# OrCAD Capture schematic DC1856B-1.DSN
size Custom
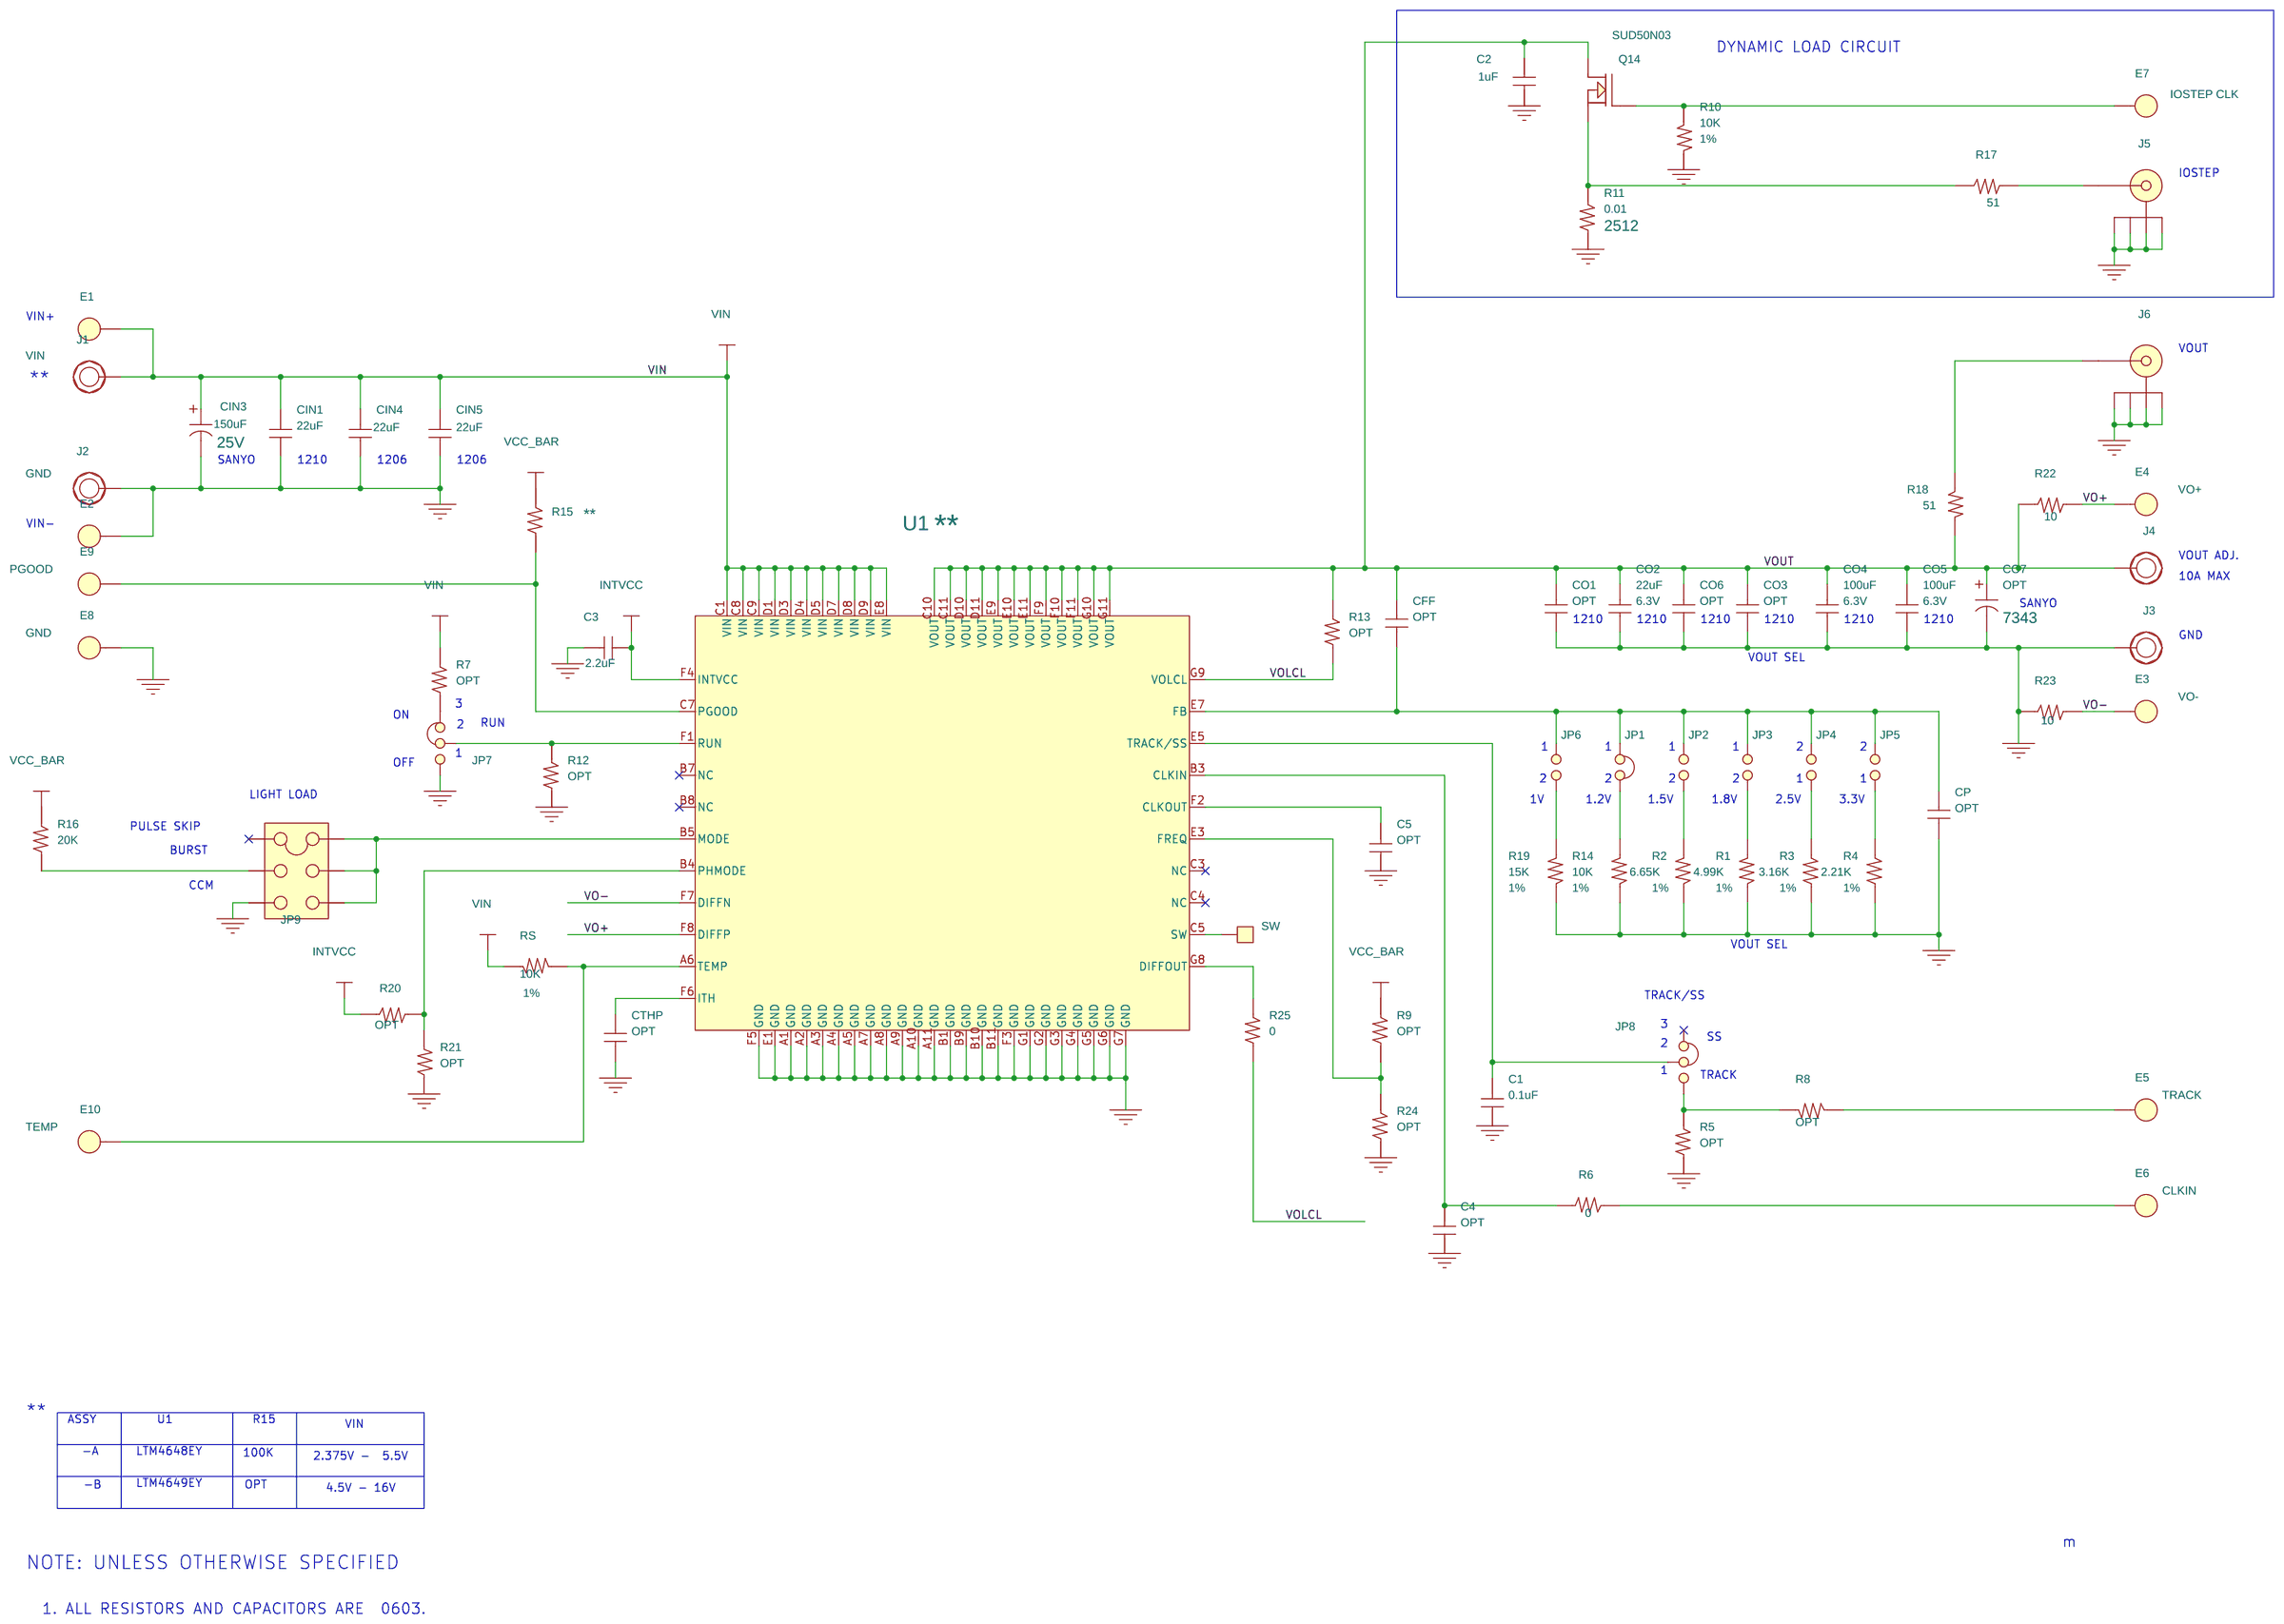
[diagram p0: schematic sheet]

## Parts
C1  0.1uF  [LG0603]
C2  1uF  [LG0603]
C3  2.2uF  [LG0603]
C4  OPT  [LG0603]
C5  OPT  [LG0603]
CFF  OPT  [LG0603]
CIN1  22uF  [LG1210]
CIN3  150uF  [CAP\SANYO\SVPA_E7]
CIN4  22uF  [1206]
CIN5  22uF  [1206]
CO1  OPT  [LG1210]
CO2  22uF  [LG1210]
CO3  OPT  [LG1210]
CO4  100uF  [LG1210]
CO5  100uF  [LG1210]
CO6  OPT  [LG1210]
CO7  OPT  [7343]
CP  OPT  [LG0603]
CTHP  OPT  [LG0603]
E1  PAD150-094  [TP\MMX\2501-2]
E2  PAD150-094  [TP\MMX\2501-2]
E3  PAD150-094  [TP\MMX\2501-2]
E4  PAD150-094  [TP\MMX\2501-2]
E5  PAD150-094  [TP\MMX\2501-2]
E6  PAD150-094  [TP\MMX\2501-2]
E7  PAD150-094  [TP\MMX\2501-2]
E8  PAD150-094  [TP\MMX\2501-2]
E9  PAD150-094  [TP\MMX\2501-2]
E10  PAD150-094  [TP\MMX\2501-2]
J1  Banana Jack  [RP325/205]
J2  Banana Jack  [RP325/205]
J3  Banana Jack  [RP325/205]
J4  Banana Jack  [RP325/205]
J5  XXX  [BNC5]
J6  XXX  [BNC5]
JP1  JMP1X2  [SIP\2P\2MM]
JP2  JMP1X2  [SIP\2P\2MM]
JP3  JMP1X2  [SIP\2P\2MM]
JP4  JMP1X2  [SIP\2P\2MM]
JP5  JMP1X2  [SIP\2P\2MM]
JP6  JMP1X2  [SIP\2P\2MM]
JP7  JMP1X3  [JUMPER3\2MM]
JP8  JMP1X3  [JUMPER3\2MM]
JP9  hdr2X3  [HDR\3X2\2MM]
Q14  SUD50N03  [TO-252]
R1  4.99K  [LG0603]
R2  6.65K  [LG0603]
R3  3.16K  [LG0603]
R4  2.21K  [LG0603]
R5  OPT  [LG0603]
R6  0  [LG0603]
R7  OPT  [LG0603]
R8  OPT  [LG0603]
R9  OPT  [LG0603]
R10  10K  [LG0603]
R11  0.01  [2512]
R12  OPT  [LG0603]
R13  OPT  [LG0603]
R14  10K  [LG0603]
R15  **  [LG0603]
R16  20K  [LG0603]
R17  51  [LG0603]
R18  51  [LG0603]
R19  15K  [LG0603]
R20  OPT  [LG0603]
R21  OPT  [LG0603]
R22  10  [LG0603]
R23  10  [LG0603]
R24  OPT  [LG0603]
R25  0  [LG0603]
RS  10K  [LG0603]
SW  SW  [RP062]
U1  **  [BGA68-15X9X4.92]
XJP1  SHUNT  [NONE]
XJP7  SHUNT  [NONE]
XJP8  SHUNT  [NONE]
XJP11  SHUNT  [NONE]

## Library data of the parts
C1 CP CTHP = CAP-NP: CAP, 0603 OPTION; Part Number: OPTION
C2 = CAP-NP: CAP, 0603 1uF 20% 10V X5R; Part Number: TAIYO YUDEN LMK107BJ105MA-T
C3 = CAP-NP: Part Number: TDK C4532X5R0J107MZ OPTION
C4 C5 = CAP-NP: CAP, 0603 1uF 20% 16V X5R OPTION; Part Number: TDK C1608X7R1C105M OPTION
CFF = CAP-NP: CAP, 0603 47pF 10% 25V NPO; Part Number: AVX 06033A470KAT
CIN1 = CAP-NP: CAP, 1812 100uF 20% 6.3V X5R OPTION; Part Number: TDK C4532X5R0J107MZ OPTION; Voltage: 16V
CIN3 = CAP: VOLTAGE: 25V
CIN4 CIN5 = CAP-NP: CAP, 0805 10uF 10% 6.3V X5R; Part Number: AVX 08056D106KAT2A; Voltage: 16V
CO1 = CAP-NP: CAP, 1812 OPTION; Part Number: TAIYO YUDEN JMK432BJ107MU-T OPTION
CO2 = CAP-NP: CAP, 1206 22uF 20% 6.3V X5R; Part Number: AVX 12066D266MAT2A; Voltage: 6.3V
CO3 CO6 = CAP-NP: CAP, 1812 100uF 20% 6.3V X5R OPTION; Part Number: TDK C4532X5R0J107MZ OPTION
CO4 CO5 = CAP-NP: CAP, 1812 100uF 20% 6.3V X5R; Part Number: TDK C4532X5R0J107MZ; Voltage: 6.3V
CO7 = CAP: VOLTAGE: 16V
E1 = E: 10th Part Field: 9V - 40V; 9th Part Field: VIN
E2 E8 = E: 10th Part Field: 9V - 40V; 9th Part Field: GND
E3 = E: 10th Part Field: XV / XA; 9th Part Field: VO-
E4 = E: 10th Part Field: XV / XA; 9th Part Field: VO+
E5 = E: 10th Part Field: XV / XA; 9th Part Field: TRACK
E6 = E: 10th Part Field: XV / XA; 9th Part Field: CLKIN
E7 = E: 10th Part Field: XV / XA; 9th Part Field: IOSTEP CLK
E9 = E: 10th Part Field: 9V - 40V; 9th Part Field: PGOOD
E10 = E: 10th Part Field: 9V - 40V; 9th Part Field: TEMP
J1-J4 = E-KEY-575_0
J5 J6 = BNC5-SCH_0: CONN,BNC,5 PINS; Part Number: CONNEX 112404
JP1-JP6 = JMP1X3_1: HEADER,2PIN, 2mm; Part Number: SAMTEC TMM 102-02-L-S
JP7 JP8 = JMP1X3_0: HEADER,3PIN, 2mm; Part Number: SAMTEC TMM-103-02-L-S
JP9 = hdr2X3_0: HEADER, 3X2 2mm; Part Number: SAMTEC  TMM-103-02-L-D
Q14 = MOSFET_N_0: XSTR,SUD50N03-10CP MOSFET; Part Number: SILICONIX SUD50N03-10CP
R1 = R: RES, 0603 4.99K OHMS 1% 1/10W; Part Number: VISHAY CRCW04024K99FKEA; Tol: 1%
R2 = R: RES, 0603 6.65K OHMS 1% 1/10W; Part Number: VISHAY CRCW06036K65FKEA; Tol: 1%
R3 = R: RES, 0603 3.16K OHMS 1% 1/10W; Part Number: VISHAY CRCW06033K16FKEA; Tol: 1%
R4 = R: RES, 0603 2.21K OHMS 1% 1/10W; Part Number: AAC CR16-2211FM; Tol: 1%
R5 R8 = R: RES, 0603 OPTION; Part Number: OPTION
R6 = R: RES, 0603 0 OHM JUMPER; Part Number: VISHAY CRCW06030000Z0EA
R7 R9 R11-R13 R15 R16 R20-R25 = R: RES, 0603 10K OHMS 5% 1/10W; Part Number: VISHAY CRCE060310K0JNEA
R10 R14 R19 RS = R: RES, 0603 9.76K OHMS 1% 1/10W; Part Number: VISHAY CRCW06039K76FKEA; Tol: 1%
R17 R18 = R: RES, 0603 51 OHMS 5% 1/10W; Part Number: AAC CR16-510JM
SW = T_POINT_R_0: PAD; Part Number: NONE
U1 = LTM4648_LTM4649: IC, LOW VOLTAGE POWER MODULE; Part Number: LINEAR TECH. LTM4608EV
XJP1 XJP7 XJP8 XJP11 = SHUNT_1: SHUNT, 2mm; Part Number: SAMTEC 2SN-BK-G

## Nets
GND: C1.1 C2.2 C3.2 C4.1 C5.1 CIN1.1 CIN3.2 CIN4.1 CIN5.1 CO1.1 CO2.1 CO3.1 CO4.1 CO5.1 CO6.1 CO7.2 CP.2 CTHP.2 E2.1(A) E8.1(A) J2.1 J3.1 J5.2 J5.3 J5.4 J5.5 J6.2 J6.3 J6.4 J6.5 JP7.1 JP9.5 R1.1 R2.1 R3.2 R4.2 R5.2 R10.2 R11.2 R12.2 R14.1 R19.1 R21.1 R23.1 R24.2 U1.A1(GND) U1.A2(GND) U1.A3(GND) U1.A4(GND) U1.A5(GND) U1.A7(GND) U1.A8(GND) U1.A9(GND) U1.A10(GND) U1.A11(GND) U1.B1(GND) U1.B9(GND) U1.B10(GND) U1.B11(GND) U1.E1(GND) U1.F3(GND) U1.F5(GND) U1.G1(GND) U1.G2(GND) U1.G3(GND) U1.G4(GND) U1.G5(GND) U1.G6(GND) U1.G7(GND)
VIN: CIN1.2 CIN3.1 CIN4.2 CIN5.2 E1.1(A) J1.1 R7.1 RS.1 U1.C1(VIN) U1.C8(VIN) U1.C9(VIN) U1.D1(VIN) U1.D3(VIN) U1.D4(VIN) U1.D5(VIN) U1.D7(VIN) U1.D8(VIN) U1.D9(VIN) U1.E8(VIN)
INTVCC: C3.1 R9.1 R15.1 R16.1 R20.1 U1.F4(INTVCC)
VO+: E4.1(A) R22.2 U1.F8(DIFFP)
VO-: E3.1(A) R23.2 U1.F7(DIFFN)
VOLCL: R13.2 R25.2 U1.G9(VOLCL)
VOUT: C2.1 CFF.1 CO1.2 CO2.2 CO3.2 CO4.2 CO5.2 CO6.2 CO7.1 J4.1 Q14.2 R13.1 R18.2 R22.1 U1.C10(VOUT) U1.C11(VOUT) U1.D10(VOUT) U1.D11(VOUT) U1.E9(VOUT) U1.E10(VOUT) U1.E11(VOUT) U1.F9(VOUT) U1.F10(VOUT) U1.F11(VOUT) U1.G10(VOUT) U1.G11(VOUT)
N17547129: JP8.1 R5.1 R8.2
N17547135: E5.1(A) R8.1
N17547173: CFF.2 CP.1 JP1.1 JP2.1 JP3.2 JP4.2 JP5.2 JP6.1 U1.E7(FB)
N17547189: JP7.2 R12.1 U1.F1(RUN)
N17547272: JP5.1 R4.1
N17547278: JP4.1 R3.1
N17547347: JP9.2 JP9.4 JP9.6 U1.B5(MODE)
N17547359: C4.2 R6.2 U1.B3(CLKIN)
N17547400: E6.1(A) R6.1
N17547499: JP1.2 R14.2
N17547555: R20.2 R21.2 U1.B4(PHMODE)
N17547701: C1.2 JP8.2 U1.E5(TRACK/SS)
N17547739: JP2.2 R2.2
N17547749: JP3.1 R1.2
N17547886: J6.1 R18.1
N17548550: E9.1(A) R15.2 U1.C7(PGOOD)
N17599383: JP9.3 R16.2
N17631871: CTHP.1 U1.F6(ITH)
N17645456: R25.1 U1.G8(DIFFOUT)
N17707931: SW.1(TP) U1.C5(SW)
N17732462: E7.1(A) Q14.1 R10.1
N17747496: J5.1 R17.2
N17748782: Q14.3 R11.1 R17.1
N17814207: JP6.2 R19.2
N17832549: C5.2 U1.F2(CLKOUT)
N17835029: R9.2 R24.1 U1.E3(FREQ)
N17849234: E10.1(A) RS.2 U1.A6(TEMP)
N18018413: JP7.3 R7.2

Not connected (* = marked no-connect by the designer): JP8 3*; JP9 1*; U1 B7(NC)* B8(NC)* C3(NC)* C4(NC)*

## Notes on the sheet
- DYNAMIC LOAD CIRCUIT
- IOSTEP
- VIN+
- VOUT
- **
- SANYO
- 1210
- 1206
- 1206
- VIN-
- VOUT ADJ.
- 10A MAX
- SANYO
- 1210
- 1210
- 1210
- 1210
- 1210
- 1210
- GND
- VOUT SEL
- ON
- 3
- 2
- RUN
- 1
- 1
- 1
- 1
- 1
- 2
- 2
- OFF
- LIGHT LOAD
- 2
- 2
- 2
- 2
- 1
- 1
- 1V
- 1.2V
- 1.5V
- 1.8V
- 2.5V
- 3.3V
- PULSE SKIP
- BURST
- CCM
- VOUT SEL
- TRACK/SS
- 3
- SS
- 2
- 1
- TRACK
- **
- ASSY
- U1
- R15
- VIN
- -A
- LTM4648EY
- 100K
- 2.375V -  5.5V
- -B
- LTM4649EY
- OPT
- 4.5V - 16V
- m
- NOTE: UNLESS OTHERWISE SPECIFIED
- 1. ALL RESISTORS AND CAPACITORS ARE  0603.
